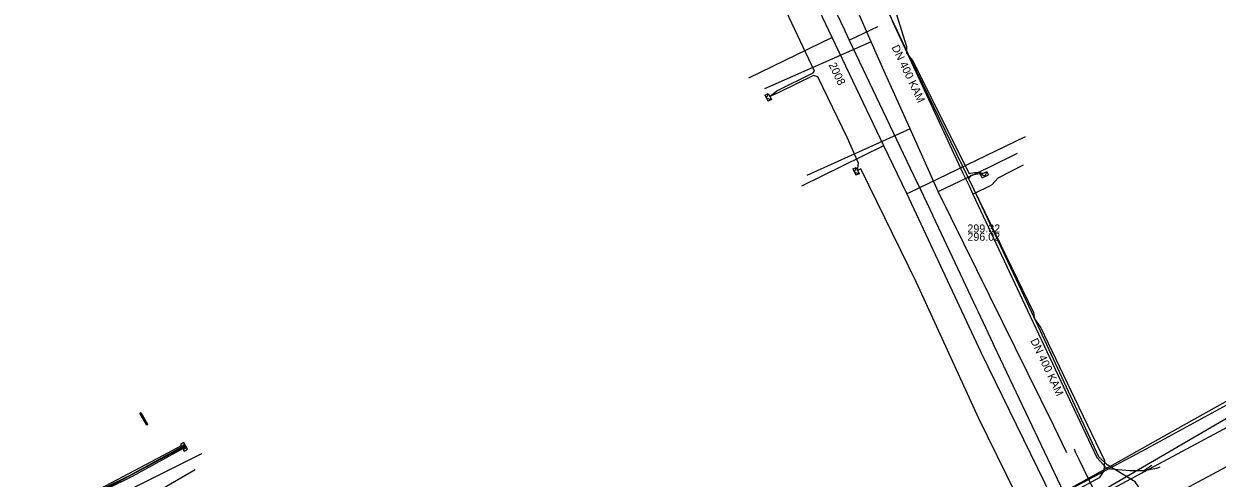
# Model space of a CAD drawing. Extents: x -600391 to -599491, y -1160176 to -1159402.
# Drawn here: x -600264.6 to -600145.4, y -1159823.2 to -1159777.8 of the extents above; entities that cross this region are included whole.
import ezdxf

# ---------------------------------------------------------------- set-up
doc = ezdxf.new("R2010")
doc.units = 0
for name, color, linetype in [('28', 7, 'Continuous'), ('31', 7, 'Continuous'), ('CETIN_linie', 7, 'Continuous'), ('UPC_ok_linie', 7, 'Continuous'), ('Vrstva 1', 7, 'Continuous'), ('Vrstva 12', 7, 'Continuous'), ('Vrstva 13', 7, 'Continuous'), ('Vrstva 15', 7, 'Continuous'), ('Vrstva 16', 7, 'Continuous'), ('Vrstva 19', 7, 'Continuous'), ('Vrstva 3', 7, 'Continuous'), ('Vrstva 42', 7, 'Continuous'), ('Vrstva 43', 7, 'Continuous'), ('Vrstva 44', 7, 'Continuous'), ('Vrstva 55', 7, 'Continuous'), ('Vrstva 58', 7, 'Continuous'), ('Vrstva 9', 7, 'Continuous')]:
    doc.layers.add(name, color=color, linetype=linetype)

# ---------------------------------------------------------------- blocks, each defined once
blk = doc.blocks.new('NN630')
at = {"layer": '31'}
for points in [[(0, -0.7), (-0.7, 0)], [(-0.7, -0.7), (-0.7, 0), (0.7, 0), (0.7, -0.7)], [(-0.7, -0.7), (0.7, -0.7)], [(0, -0.7), (0.7, 0)]]:
    blk.add_lwpolyline(points, dxfattribs=at)
blk = doc.blocks.new('NN620')
at = {"layer": '28'}
for points in [[(0.75, 0), (-0.75, 0)], [(-0.75, 0), (-0.75, -0.75)], [(0.75, -0.75), (0.75, 0)], [(-0.75, -0.75), (0.75, -0.75)], [(0.37, -0.18), (-0.38, -0.18)], [(-0.38, -0.18), (-0.38, -0.56)], [(-0.38, -0.56), (0.37, -0.56)], [(0.32, -0.23), (-0.33, -0.23)], [(-0.33, -0.23), (-0.33, -0.51)], [(-0.33, -0.51), (0.32, -0.51)], [(0.27, -0.27), (-0.28, -0.27)], [(-0.28, -0.27), (-0.28, -0.46)], [(-0.28, -0.46), (0.27, -0.46)], [(0.23, -0.32), (-0.23, -0.32)], [(-0.23, -0.32), (-0.23, -0.42)], [(-0.23, -0.42), (0.23, -0.42)], [(-0.19, -0.37), (0.19, -0.37)], [(0.23, -0.42), (0.23, -0.32)], [(0.27, -0.46), (0.27, -0.27)], [(0.32, -0.51), (0.32, -0.23)], [(0.37, -0.56), (0.37, -0.18)]]:
    blk.add_lwpolyline(points, dxfattribs=at)

msp = doc.modelspace()

# ---------------------------------------------------------------- linework, layer by layer
at = {"layer": 'CETIN_linie'}
msp.add_lwpolyline([(-600155.82, -1159824.25), (-600096.42, -1159792.4), (-600032.25, -1159754.89)], dxfattribs=at)
at = {"layer": 'UPC_ok_linie'}
msp.add_line((-600152.7, -1159822.44), (-600151.92, -1159821.9), dxfattribs=at)
for points in [[(-600177.86, -1159777.5), (-600170.81, -1159792.72), (-600170.15, -1159793.98), (-600169.79, -1159794.82)], [(-600169.79, -1159794.82), (-600167.9, -1159793.88), (-600167.26, -1159793.18), (-600164.75, -1159791.9)], [(-600169.79, -1159794.82), (-600164.32, -1159806.44), (-600157.4, -1159821.16), (-600156.4, -1159822.23), (-600154.09, -1159822.43), (-600152.7, -1159822.44)], [(-600152.7, -1159822.44), (-600151.43, -1159822.21), (-600151.06, -1159822.08)]]:
    msp.add_lwpolyline(points, dxfattribs=at)
at = {"layer": 'Vrstva 1'}
msp.add_lwpolyline([(-600179.33, -1159778.09), (-600182.11, -1159779.43)], dxfattribs=at)
at = {"layer": 'Vrstva 13'}
for points in [[(-600161.18, -1159826.62), (-600168.95, -1159810.66), (-600176.39, -1159794.77), (-600178.7, -1159789.98), (-600183.86, -1159779.17), (-600184.83, -1159777.12), (-600190.37, -1159765.45), (-600191.37, -1159763.33), (-600196.96, -1159751.61), (-600199.19, -1159746.92), (-600201.13, -1159742.84), (-600201.62, -1159741.81), (-600205.05, -1159734.61), (-600208.57, -1159727.22), (-600210.91, -1159722.31), (-600212.83, -1159718.29), (-600213.07, -1159717.78), (-600218.37, -1159706.66), (-600223.5, -1159695.91), (-600225.68, -1159691.33), (-600227.32, -1159687.89), (-600233.15, -1159675.83), (-600235.99, -1159670.03)], [(-600183.86, -1159779.17), (-600183.93, -1159779.21), (-600192.21, -1159783.24)], [(-600176.39, -1159794.77), (-600176.21, -1159794.69), (-600164.54, -1159789.07)], [(-600178.7, -1159789.98), (-600178.78, -1159790.02), (-600186.92, -1159794.03)], [(-600263.68, -1159829.99), (-600263.57, -1159829.92), (-600258.86, -1159826.76), (-600246.85, -1159820.76)]]:
    msp.add_lwpolyline(points, dxfattribs=at)
at = {"layer": 'Vrstva 16'}
for points in [[(-600160.4, -1159820.68), (-600161.71, -1159817.97), (-600173.25, -1159794.55), (-600176.06, -1159788.29), (-600178.68, -1159782.46), (-600179.95, -1159779.58), (-600182.83, -1159773.03)], [(-600179.95, -1159779.58), (-600190.61, -1159784.29)], [(-600176.06, -1159788.29), (-600186.4, -1159792.94)], [(-600173.25, -1159794.55), (-600168.1, -1159792.09), (-600165.33, -1159790.73)]]:
    msp.add_lwpolyline(points, dxfattribs=at)
at = {"layer": 'Vrstva 19'}
for points in [[(-600155.51, -1159827.83), (-600155.66, -1159827.54), (-600156.28, -1159827.12), (-600156.44, -1159826.82), (-600156.71, -1159826.45), (-600159.16, -1159821.35), (-600159.52, -1159820.6), (-600159.65, -1159820.33)], [(-600141.71, -1159820.61), (-600150.98, -1159825.58), (-600155.51, -1159827.83), (-600156.15, -1159828.15), (-600156.98, -1159828.56), (-600160.11, -1159830.11), (-600160.89, -1159830.52), (-600162.36, -1159831.29)], [(-600247.52, -1159822.38), (-600251.41, -1159824.64), (-600254.69, -1159826.25), (-600259.17, -1159828.58), (-600259.44, -1159828.72), (-600264.53, -1159831.56)]]:
    msp.add_lwpolyline(points, dxfattribs=at)
at = {"layer": 'Vrstva 3'}
msp.add_lwpolyline([(-600252.95, -1159816.64), (-600252.27, -1159817.81), (-600252.35, -1159817.91), (-600253.06, -1159816.71)], close=True, dxfattribs=at)
at = {"layer": 'Vrstva 42'}
for points in [[(-600180.58, -1159834.93), (-600165.45, -1159826.72), (-600164.94, -1159826.41), (-600164.92, -1159825.76), (-600165.47, -1159824.84), (-600169.23, -1159817.19), (-600175.43, -1159803.66), (-600180.98, -1159792.28), (-600181.32, -1159792.46), (-600181.24, -1159791.71), (-600182.32, -1159789.21), (-600185.29, -1159783.1), (-600185.72, -1159782.95), (-600189.24, -1159784.69), (-600190.1, -1159785.06), (-600189.37, -1159784.49), (-600185.74, -1159782.68), (-600185.62, -1159782.53), (-600190.14, -1159772.91)], [(-600177.95, -1159775.13), (-600176.42, -1159780.07), (-600176.43, -1159780.73), (-600175.9, -1159781.32), (-600170.15, -1159792.74), (-600169.45, -1159792.61), (-600168.7, -1159792.71), (-600169.51, -1159792.87), (-600170.01, -1159792.97), (-600170.22, -1159793.27), (-600163.75, -1159806.64), (-600163.62, -1159807.28), (-600162.99, -1159808.18), (-600159.62, -1159815.21), (-600156.65, -1159821.45), (-600156.7, -1159822.49), (-600157.17, -1159823.17), (-600163.17, -1159826.43), (-600163.95, -1159826.46), (-600164.69, -1159826.56), (-600165.32, -1159826.93), (-600180.45, -1159835.18), (-600180.95, -1159835.33), (-600181.08, -1159835.24)], [(-600140.79, -1159813.9), (-600152.87, -1159820.51), (-600163.16, -1159825.99), (-600167.31, -1159828.23), (-600173.76, -1159831.51), (-600180.6, -1159835.48), (-600181.14, -1159835.31)], [(-600248.79, -1159820.17), (-600250.58, -1159821.13), (-600259.35, -1159825.82), (-600266.34, -1159825.25), (-600273.31, -1159829.48), (-600273.68, -1159830.56), (-600270.51, -1159835.78), (-600269.48, -1159836.81), (-600267.65, -1159835.87), (-600265.67, -1159839.42), (-600270.48, -1159842.19)], [(-600248.91, -1159819.99), (-600250.73, -1159820.95), (-600259.4, -1159825.56), (-600266.4, -1159824.99)], [(-600204.77, -1159847.02), (-600204.95, -1159847.26), (-600205.01, -1159848.39), (-600204.77, -1159849.41), (-600205.48, -1159850.61), (-600206.89, -1159851.24), (-600211.53, -1159853.59), (-600218.76, -1159857.52), (-600227.23, -1159862.31), (-600234.6, -1159866.67), (-600235.46, -1159866.44), (-600236.46, -1159865.22), (-600238.22, -1159861.82), (-600242.58, -1159853.81), (-600243.04, -1159851.44), (-600245.65, -1159846.23), (-600250.48, -1159837.22), (-600255.07, -1159829.25), (-600257.08, -1159825.39), (-600256.5, -1159824.13), (-600253.89, -1159822.83), (-600248.84, -1159820.08)], [(-600204.93, -1159846.9), (-600205.15, -1159847.18), (-600205.21, -1159848.41), (-600204.99, -1159849.37), (-600205.62, -1159850.45), (-600206.97, -1159851.06), (-600211.63, -1159853.41), (-600218.86, -1159857.34), (-600227.33, -1159862.13), (-600234.62, -1159866.45), (-600235.34, -1159866.26), (-600236.3, -1159865.1), (-600238.04, -1159861.72), (-600242.38, -1159853.75), (-600242.84, -1159851.38), (-600250.3, -1159837.12), (-600254.89, -1159829.15), (-600256.86, -1159825.39), (-600256.34, -1159824.27), (-600253.79, -1159823.01), (-600248.74, -1159820.26)]]:
    msp.add_lwpolyline(points, dxfattribs=at)
at = {"layer": 'Vrstva 44'}
msp.add_lwpolyline([(-600163.23, -1159825.99), (-600157.45, -1159822.77), (-600154.97, -1159821.42), (-600150.7, -1159819.03), (-600143.39, -1159814.93)], dxfattribs=at)
at = {"layer": 'Vrstva 55'}
msp.add_lwpolyline([(-600149.35, -1159833.54), (-600149.95, -1159832.72), (-600150.3, -1159832.01), (-600153.14, -1159824.2), (-600153.57, -1159823.58), (-600156.38, -1159821.89), (-600157.19, -1159821.09), (-600163.91, -1159806.66), (-600169.65, -1159794.38), (-600176.01, -1159781.35), (-600182.61, -1159767.26)], dxfattribs=at)
at = {"layer": 'Vrstva 58'}
msp.add_lwpolyline([(-600220.16, -1159921.24), (-600245.97, -1159874.15), (-600235.6, -1159868.36), (-600209.3, -1159854.36), (-600163.55, -1159828.33), (-600142.16, -1159815.89)], dxfattribs=at)
at = {"layer": 'Vrstva 9'}
for points in [[(-600171.83, -1159801.11), (-600173.77, -1159797.02), (-600173.81, -1159796.93), (-600175.31, -1159793.77), (-600175.37, -1159793.65), (-600182.11, -1159779.46), (-600182.15, -1159779.38), (-600182.51, -1159778.61), (-600182.6, -1159778.42), (-600184.13, -1159775.21)], [(-600157.53, -1159831.32), (-600167.65, -1159809.99), (-600167.76, -1159809.75), (-600169.24, -1159806.62), (-600169.46, -1159806.15), (-600171.83, -1159801.11)]]:
    msp.add_lwpolyline(points, dxfattribs=at)

# ---------------------------------------------------------------- block references
at = {"layer": 'Vrstva 43'}
for name, p, xscale, yscale, rotation in [('NN630', (-600190.1, -1159785.06), 0.49999999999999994, 0.5000000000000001, -62.00000000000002), ('NN630', (-600181.32, -1159792.46), 0.5000000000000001, 0.4999999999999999, -64), ('NN630', (-600168.7, -1159792.71), 0.49999999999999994, 0.5000000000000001, 25), ('NN620', (-600248.79, -1159820.17), 0.5000000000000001, 0.4999999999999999, 119)]:
    msp.add_blockref(name, p, dxfattribs=dict(at, xscale=xscale, yscale=yscale, rotation=rotation))

# ---------------------------------------------------------------- texts
at = {"layer": 'Vrstva 12'}
for rotation, p in [(295.417, (-600177.94, -1159780.13)), (295.3597, (-600164.07, -1159809.45))]:
    msp.add_text('DN 400 KAM', height=0.8, rotation=rotation, dxfattribs=at).set_placement(p)
for s, p in [('299.32', (-600170.34, -1159798.65)), ('296.02', (-600170.34, -1159799.48))]:
    msp.add_text(s, height=0.8, dxfattribs=at).set_placement(p)
at = {"layer": 'Vrstva 15'}
msp.add_text('2008', height=0.8, rotation=295.417, dxfattribs=at).set_placement((-600184.23, -1159781.88))

doc.saveas('drawing.dxf')
